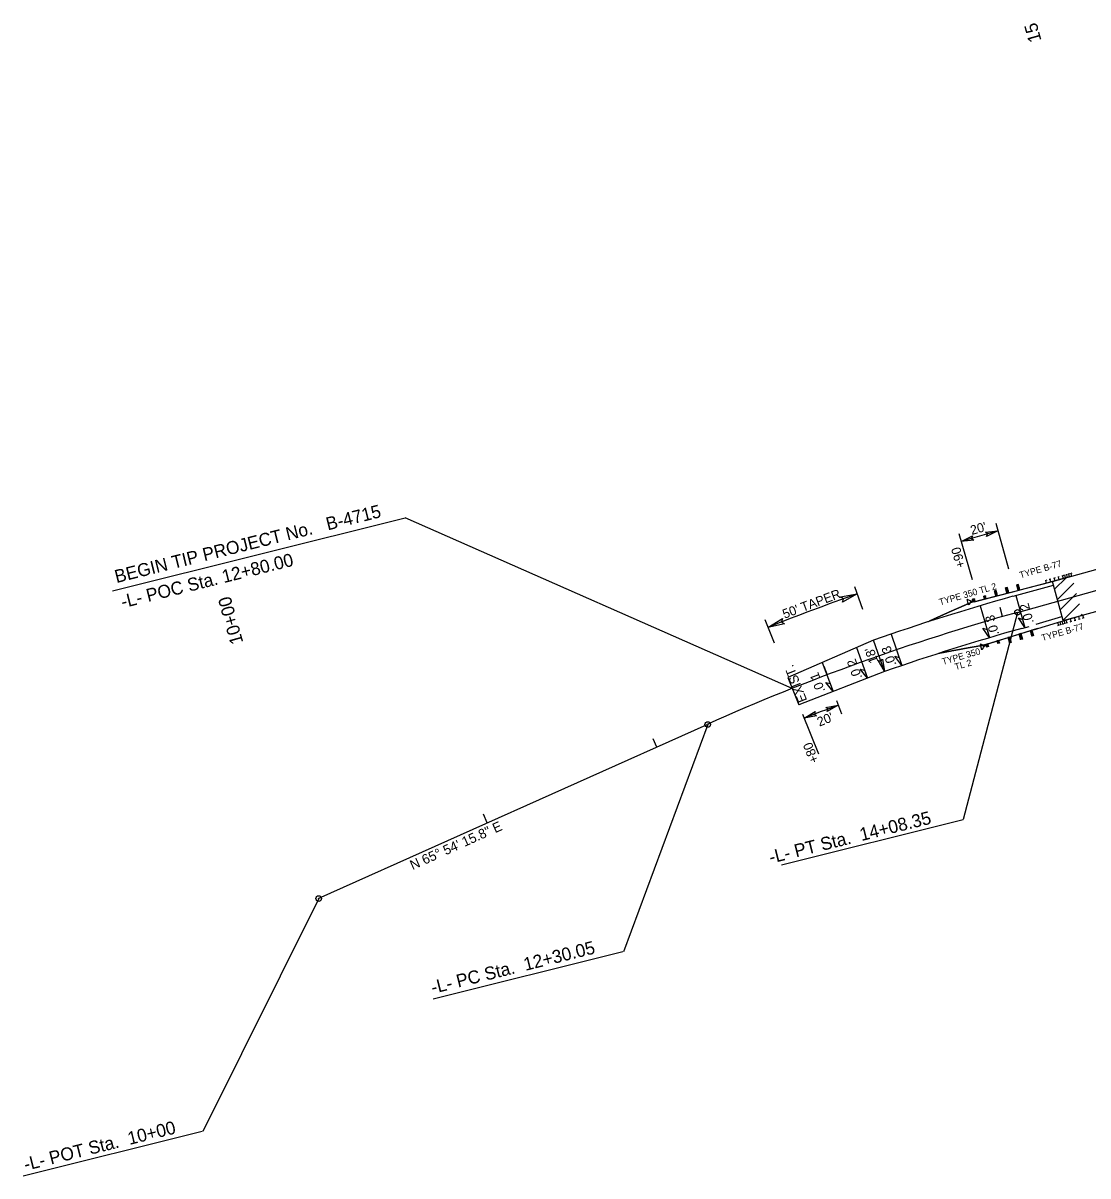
# Model space of a CAD drawing. Extents: x 1030774 to 1032138, y 656382 to 657027.
# Drawn here: x 1030774 to 1031349, y 656382 to 657004 of the extents above; entities that cross this region are included whole.
import ezdxf

# ---------------------------------------------------------------- set-up
doc = ezdxf.new("R2010")
doc.units = 0
for name, color, linetype in [('Prop Approach Slab', 7, 'Continuous'), ('Prop Approach Slab Hatching', 7, 'Continuous'), ('Prop Dimension Text', 7, 'Continuous'), ('Prop EOT', 7, 'Continuous'), ('Prop Guardrail', 7, 'Continuous'), ('Prop Guardrail Anchor Unit CELL', 7, 'Continuous'), ('Prop Horizontal Alignment', 7, 'Continuous'), ('Prop Horizontal Alignment Direction Label', 7, 'Continuous'), ('Prop Horizontal Alignment Station Label', 7, 'Continuous'), ('Prop Horizontal Alignment Tick Label', 7, 'Continuous'), ('Prop Horizontal Alignment Tick Small', 7, 'Continuous'), ('Prop Paved Shoulder', 7, 'Continuous'), ('Prop Roadway Bridge', 7, 'Continuous'), ('Prop SBG', 7, 'Continuous'), ('Prop Structure Anchor Unit CELL', 7, 'Continuous'), ('Prop Superelevation  Arrow CELL', 7, 'Continuous'), ('Prop Superelevation Label', 7, 'Continuous'), ('Prop Terminator CELL', 7, 'Continuous')]:
    doc.layers.add(name, color=color, linetype=linetype)

msp = doc.modelspace()

# ---------------------------------------------------------------- linework, layer by layer
at = {"layer": 'Prop Approach Slab'}
for p, q in [((1031329.55, 656702.31), (1031340.03, 656705.23)), ((1031335.42, 656681.27), (1031329.55, 656702.31)), ((1031335.42, 656681.27), (1031345.9, 656684.2))]:
    msp.add_line(p, q, dxfattribs=at)
at = {"layer": 'Prop Approach Slab Hatching'}
for p, q in [((1031330.77, 656698.17), (1031336.99, 656704.38)), ((1031332.32, 656692.64), (1031341.09, 656701.42)), ((1031333.86, 656687.11), (1031342.63, 656695.89)), ((1031335.4, 656681.59), (1031344.18, 656690.36)), ((1031344.77, 656683.88), (1031345.72, 656684.83))]:
    msp.add_line(p, q, dxfattribs=at)
at = {"layer": 'Prop Dimension Text'}
for p, q in [((1031227.25, 656687.19), (1031222.95, 656699.45)), ((1031174.37, 656681.8), (1031179.35, 656669.32)), ((1031238.98, 656653.74), (1031233.02, 656670.72))]:
    msp.add_line(p, q, dxfattribs=at)
msp.add_arc((1031633.08, 655529.83), 1235.44, 109.32356, 111.71226, dxfattribs=at)
at = {"layer": 'Prop EOT'}
for p, q in [((1031308.32, 656694.4), (1031330.13, 656700.48)), ((1031313.15, 656677.06), (1031316.96, 656678.12)), ((1031233.02, 656670.72), (1031186.82, 656650.61)), ((1031186.82, 656650.61), (1031192.7, 656635.85)), ((1031238.99, 656653.74), (1031192.7, 656635.85))]:
    msp.add_line(p, q, dxfattribs=at)
for radius, end in [(1209, 109.32387), (1191, 109.32325)]:
    msp.add_arc((1031633.08, 655529.83), radius, 105.58244, end, dxfattribs=at)
at = {"layer": 'Prop Guardrail'}
for p, q in [((1031326.48, 656701.46), (1031312.07, 656697.79)), ((1031319.43, 656676.32), (1031332.29, 656680.23))]:
    msp.add_line(p, q, dxfattribs=at)
at = {"layer": 'Prop Guardrail Anchor Unit CELL'}
for p, q in [((1031305.26, 656699.2), (1031304.29, 656698.95)), ((1031305.04, 656696.01), (1031304.29, 656698.95)), ((1031304.29, 656698.95), (1031305.64, 656697.73)), ((1031304.67, 656697.48), (1031305.26, 656699.2)), ((1031306.01, 656696.26), (1031305.26, 656699.2)), ((1031311.31, 656700.75), (1031310.35, 656700.5)), ((1031311.1, 656697.56), (1031310.35, 656700.5)), ((1031310.35, 656700.5), (1031311.69, 656699.28)), ((1031310.72, 656699.03), (1031311.31, 656700.75)), ((1031311.69, 656699.28), (1031310.72, 656699.03)), ((1031312.07, 656697.81), (1031310.72, 656699.03)), ((1031311.69, 656699.28), (1031311.1, 656697.56)), ((1031312.07, 656697.81), (1031311.31, 656700.75)), ((1031283.8, 656692.74), (1031283.5, 656692.66)), ((1031283.8, 656692.74), (1031285.15, 656692.2)), ((1031287.47, 656693.08), (1031286.5, 656692.84)), ((1031286.88, 656691.36), (1031286.5, 656692.84)), ((1031287.85, 656691.61), (1031286.5, 656692.84)), ((1031287.47, 656693.08), (1031286.88, 656691.36)), ((1031287.36, 656691.49), (1031311.58, 656697.68)), ((1031287.85, 656691.61), (1031287.47, 656693.08)), ((1031293.53, 656694.63), (1031292.56, 656694.38)), ((1031292.93, 656692.91), (1031292.56, 656694.38)), ((1031293.9, 656693.16), (1031292.56, 656694.38)), ((1031293.53, 656694.63), (1031292.93, 656692.91)), ((1031293.9, 656693.16), (1031292.93, 656692.91)), ((1031293.9, 656693.16), (1031293.53, 656694.63)), ((1031299.2, 656697.65), (1031298.24, 656697.4)), ((1031298.99, 656694.46), (1031298.24, 656697.4)), ((1031298.24, 656697.4), (1031299.58, 656696.18)), ((1031298.61, 656695.93), (1031299.2, 656697.65)), ((1031299.58, 656696.18), (1031298.61, 656695.93)), ((1031299.96, 656694.71), (1031298.61, 656695.93)), ((1031299.58, 656696.18), (1031298.99, 656694.46)), ((1031299.96, 656694.71), (1031298.99, 656694.46)), ((1031299.96, 656694.71), (1031299.2, 656697.65)), ((1031305.64, 656697.73), (1031304.67, 656697.48)), ((1031306.01, 656696.26), (1031304.67, 656697.48)), ((1031305.64, 656697.73), (1031305.04, 656696.01)), ((1031306.01, 656696.26), (1031305.04, 656696.01)), ((1031312.07, 656697.81), (1031311.1, 656697.56)), ((1031284.22, 656689.81), (1031283.5, 656692.66)), ((1031284.52, 656689.89), (1031284.22, 656689.81)), ((1031285.45, 656691.01), (1031284.52, 656689.89)), ((1031285.15, 656692.2), (1031285.45, 656691.01)), ((1031285.27, 656691.71), (1031286.7, 656692.07)), ((1031286.88, 656691.37), (1031285.45, 656691.01)), ((1031287.85, 656691.61), (1031286.88, 656691.36)), ((1031294.09, 656668.6), (1031317.99, 656675.92)), ((1031312.49, 656674.24), (1031311.54, 656673.95)), ((1031312.49, 656674.24), (1031311.98, 656672.5)), ((1031312.49, 656674.24), (1031313.38, 656671.34)), ((1031318.47, 656676.07), (1031317.51, 656675.78)), ((1031317.51, 656675.78), (1031318.4, 656672.88)), ((1031318.91, 656674.62), (1031317.51, 656675.78)), ((1031318.47, 656676.07), (1031317.96, 656674.33)), ((1031318.91, 656674.62), (1031317.96, 656674.33)), ((1031317.96, 656674.33), (1031319.36, 656673.17)), ((1031318.4, 656672.88), (1031318.91, 656674.62)), ((1031318.47, 656676.07), (1031319.36, 656673.17)), ((1031290.83, 656668.49), (1031290.54, 656668.4)), ((1031290.54, 656668.4), (1031291.4, 656665.59)), ((1031292.21, 656668.01), (1031290.83, 656668.49)), ((1031293.61, 656668.44), (1031292.21, 656668.01)), ((1031292.57, 656666.84), (1031292.21, 656668.01)), ((1031294.57, 656668.75), (1031293.61, 656668.45)), ((1031293.61, 656668.45), (1031294.05, 656667)), ((1031295.01, 656667.3), (1031293.61, 656668.45)), ((1031294.57, 656668.75), (1031294.05, 656667)), ((1031294.57, 656668.75), (1031295.01, 656667.3)), ((1031300.54, 656670.58), (1031299.58, 656670.28)), ((1031299.58, 656670.28), (1031300.03, 656668.83)), ((1031300.99, 656669.13), (1031299.58, 656670.28)), ((1031300.54, 656670.58), (1031300.03, 656668.83)), ((1031300.99, 656669.13), (1031300.03, 656668.83)), ((1031300.54, 656670.58), (1031300.99, 656669.13)), ((1031306.52, 656672.41), (1031305.56, 656672.12)), ((1031305.56, 656672.12), (1031306.45, 656669.21)), ((1031306.96, 656670.96), (1031305.56, 656672.12)), ((1031306.52, 656672.41), (1031306.01, 656670.66)), ((1031306.96, 656670.96), (1031306.01, 656670.66)), ((1031306.01, 656670.66), (1031307.41, 656669.51)), ((1031306.45, 656669.21), (1031306.96, 656670.96)), ((1031307.41, 656669.51), (1031306.45, 656669.21)), ((1031306.52, 656672.41), (1031307.41, 656669.51)), ((1031311.54, 656673.95), (1031312.43, 656671.04)), ((1031312.94, 656672.79), (1031311.54, 656673.95)), ((1031312.94, 656672.79), (1031311.98, 656672.5)), ((1031311.98, 656672.5), (1031313.38, 656671.34)), ((1031312.43, 656671.04), (1031312.94, 656672.79)), ((1031313.38, 656671.34), (1031312.43, 656671.04)), ((1031319.36, 656673.17), (1031318.4, 656672.88)), ((1031291.69, 656665.68), (1031291.4, 656665.59)), ((1031291.69, 656665.68), (1031292.57, 656666.84)), ((1031292.42, 656667.32), (1031293.82, 656667.76)), ((1031295.01, 656667.3), (1031294.05, 656667))]:
    msp.add_line(p, q, dxfattribs=at)
at = {"layer": 'Prop Horizontal Alignment'}
for p, q in [((1031310.74, 656685.73), (1031475.4, 656731.65)), ((1030933.16, 656531.35), (1031143.17, 656625.27))]:
    msp.add_line(p, q, dxfattribs=at)
msp.add_arc((1031633.09, 655529.83), 1200, 105.58243, 114.09562, dxfattribs=at)
at = {"layer": 'Prop Horizontal Alignment Station Label'}
for p, q in [((1030822.29, 656697.3), (1030980.18, 656736.67)), ((1031189.18, 656644.71), (1030980.18, 656736.67)), ((1031310.74, 656685.73), (1031281.34, 656573.84)), ((1031143.54, 656625.18), (1031098.1, 656502.57)), ((1031183.41, 656549.43), (1031281.34, 656573.84)), ((1030933.53, 656531.26), (1030870.95, 656405.55)), ((1030995.33, 656477.13), (1031097.74, 656502.67)), ((1030773.93, 656381.55), (1030870.59, 656405.65))]:
    msp.add_line(p, q, dxfattribs=at)
for centre in [(1031310.74, 656685.73), (1031143.54, 656625.18), (1030933.53, 656531.26)]:
    msp.add_circle(centre, 1.5, dxfattribs=at)
at = {"layer": 'Prop Horizontal Alignment Tick Small'}
for p, q in [((1031302.7, 656683.45), (1031301.32, 656688.26)), ((1031208.18, 656651.86), (1031206.41, 656656.53)), ((1031116.1, 656612.91), (1031114.06, 656617.47)), ((1031024.45, 656572.18), (1031022.41, 656576.74))]:
    msp.add_line(p, q, dxfattribs=at)
at = {"layer": 'Prop Paved Shoulder'}
for p, q in [((1031285.45, 656691.01), (1031329.55, 656702.31)), ((1031321.53, 656676.97), (1031292.36, 656667.92))]:
    msp.add_line(p, q, dxfattribs=at)
for points in [[(1031285.47, 656690.91), (1031285.16, 656690.78), (1031284.84, 656690.64), (1031284.52, 656690.5), (1031284.21, 656690.37), (1031283.89, 656690.23), (1031283.58, 656690.09), (1031283.26, 656689.95), (1031282.94, 656689.82), (1031282.63, 656689.68), (1031282.31, 656689.54), (1031282, 656689.4), (1031281.68, 656689.26), (1031281.37, 656689.13), (1031281.05, 656688.99), (1031280.73, 656688.85), (1031280.42, 656688.71), (1031280.1, 656688.57), (1031279.79, 656688.43), (1031279.47, 656688.3), (1031279.16, 656688.16), (1031278.84, 656688.02), (1031278.53, 656687.88), (1031278.21, 656687.74), (1031277.9, 656687.6), (1031277.58, 656687.46), (1031277.27, 656687.32), (1031276.95, 656687.18), (1031276.64, 656687.04), (1031276.32, 656686.9), (1031276.01, 656686.77), (1031275.69, 656686.63), (1031275.38, 656686.49), (1031275.06, 656686.35), (1031274.75, 656686.21), (1031274.43, 656686.07), (1031274.12, 656685.93), (1031273.8, 656685.79), (1031273.49, 656685.65), (1031273.18, 656685.51), (1031272.86, 656685.37), (1031272.55, 656685.22), (1031272.23, 656685.08), (1031271.92, 656684.94), (1031271.6, 656684.8), (1031271.29, 656684.66), (1031270.98, 656684.52), (1031270.66, 656684.38), (1031270.35, 656684.24), (1031270.04, 656684.1), (1031269.72, 656683.96), (1031269.41, 656683.82), (1031269.09, 656683.67), (1031268.78, 656683.53), (1031268.47, 656683.39), (1031268.15, 656683.25), (1031267.84, 656683.11), (1031267.53, 656682.97), (1031267.21, 656682.82), (1031266.9, 656682.68), (1031266.59, 656682.54), (1031266.27, 656682.4), (1031265.96, 656682.25), (1031265.65, 656682.11), (1031265.33, 656681.97), (1031265.02, 656681.83), (1031264.71, 656681.68), (1031264.39, 656681.54), (1031264.08, 656681.4), (1031263.77, 656681.26), (1031263.46, 656681.11), (1031263.14, 656680.97), (1031262.83, 656680.83), (1031262.21, 656680.54)], [(1031292.36, 656667.92), (1031292.02, 656667.87), (1031291.69, 656667.81), (1031291.36, 656667.75), (1031291.02, 656667.69), (1031290.69, 656667.63), (1031290.36, 656667.58), (1031290.03, 656667.52), (1031289.69, 656667.46), (1031289.36, 656667.4), (1031289.03, 656667.34), (1031288.69, 656667.29), (1031288.36, 656667.23), (1031288.03, 656667.17), (1031287.69, 656667.11), (1031287.36, 656667.05), (1031287.03, 656666.99), (1031286.7, 656666.93), (1031286.36, 656666.87), (1031286.03, 656666.81), (1031285.7, 656666.76), (1031285.36, 656666.7), (1031285.03, 656666.64), (1031284.7, 656666.58), (1031284.37, 656666.52), (1031284.03, 656666.46), (1031283.7, 656666.4), (1031283.37, 656666.34), (1031283.03, 656666.28), (1031282.7, 656666.22), (1031282.37, 656666.16), (1031282.03, 656666.1), (1031281.7, 656666.04), (1031281.37, 656665.98), (1031281.04, 656665.92), (1031280.7, 656665.85), (1031280.37, 656665.79), (1031280.04, 656665.73), (1031279.7, 656665.67), (1031279.37, 656665.61), (1031279.04, 656665.55), (1031278.71, 656665.49), (1031278.37, 656665.43), (1031278.04, 656665.36), (1031277.71, 656665.3), (1031277.38, 656665.24), (1031277.04, 656665.18), (1031276.71, 656665.12), (1031276.38, 656665.06), (1031276.04, 656664.99), (1031275.71, 656664.93), (1031275.38, 656664.87), (1031275.05, 656664.81), (1031274.71, 656664.74), (1031274.38, 656664.68), (1031274.05, 656664.62), (1031273.71, 656664.56), (1031273.38, 656664.49), (1031273.05, 656664.43), (1031272.72, 656664.37), (1031272.38, 656664.3), (1031272.05, 656664.24), (1031271.72, 656664.18), (1031271.39, 656664.11), (1031271.05, 656664.05), (1031270.72, 656663.99), (1031270.39, 656663.92), (1031270.06, 656663.86), (1031269.72, 656663.79), (1031269.39, 656663.73), (1031269.06, 656663.67), (1031268.72, 656663.6), (1031268.39, 656663.54), (1031267.73, 656663.41)]]:
    msp.add_spline(points, degree=3, dxfattribs=at)
at = {"layer": 'Prop Roadway Bridge'}
for p, q in [((1031340.03, 656705.23), (1031457.91, 656738.11)), ((1031345.9, 656684.2), (1031463.78, 656717.07))]:
    msp.add_line(p, q, dxfattribs=at)
at = {"layer": 'Prop SBG'}
msp.add_line((1031320.85, 656679.4), (1031334.75, 656683.49), dxfattribs=at)
at = {"layer": 'Prop Structure Anchor Unit CELL'}
for p, q in [((1031340.03, 656705.23), (1031326.48, 656701.46)), ((1031335.52, 656705.53), (1031334.7, 656705.3)), ((1031335.51, 656703.97), (1031335.11, 656705.42)), ((1031336.65, 656705.85), (1031335.83, 656705.62)), ((1031336.64, 656704.29), (1031336.24, 656705.73)), ((1031337.78, 656706.16), (1031336.95, 656705.93)), ((1031337.77, 656704.6), (1031337.37, 656706.05)), ((1031338.91, 656706.48), (1031338.08, 656706.25)), ((1031338.9, 656704.92), (1031338.5, 656706.36)), ((1031340.04, 656706.79), (1031339.21, 656706.56)), ((1031340.03, 656705.23), (1031339.63, 656706.68)), ((1031326.49, 656703.02), (1031325.67, 656702.78)), ((1031326.48, 656701.46), (1031326.08, 656702.9)), ((1031328.75, 656703.64), (1031327.92, 656703.41)), ((1031328.74, 656702.08), (1031328.34, 656703.53)), ((1031331.01, 656704.27), (1031330.18, 656704.04)), ((1031331, 656702.71), (1031330.6, 656704.16)), ((1031333.27, 656704.9), (1031332.44, 656704.67)), ((1031333.26, 656703.34), (1031332.85, 656704.79)), ((1031332.42, 656680.27), (1031345.91, 656684.22)), ((1031333.54, 656680.6), (1031333.96, 656679.16)), ((1031334.67, 656680.93), (1031335.09, 656679.49)), ((1031335.79, 656681.26), (1031336.21, 656679.82)), ((1031336.92, 656681.59), (1031337.34, 656680.15)), ((1031339.17, 656682.24), (1031339.59, 656680.8)), ((1031339.18, 656680.68), (1031340, 656680.93)), ((1031341.42, 656682.9), (1031341.84, 656681.46)), ((1031341.42, 656681.34), (1031342.25, 656681.58)), ((1031343.67, 656683.56), (1031344.09, 656682.12)), ((1031343.67, 656682), (1031344.5, 656682.24)), ((1031345.91, 656684.22), (1031346.34, 656682.78)), ((1031345.92, 656682.66), (1031346.75, 656682.9)), ((1031332.42, 656680.27), (1031332.84, 656678.83)), ((1031332.43, 656678.71), (1031333.25, 656678.95)), ((1031333.55, 656679.04), (1031334.38, 656679.28)), ((1031334.68, 656679.37), (1031335.5, 656679.61)), ((1031335.8, 656679.7), (1031336.63, 656679.94)), ((1031336.93, 656680.03), (1031337.75, 656680.27))]:
    msp.add_line(p, q, dxfattribs=at)
at = {"layer": 'Prop Superelevation  Arrow CELL'}
for p, q in [((1031309.9, 656694.84), (1031314.74, 656677.5)), ((1031290.54, 656689.29), (1031295.64, 656672.03)), ((1031242.54, 656674.02), (1031248.36, 656656.98)), ((1031223.77, 656666.69), (1031229.72, 656650.16)), ((1031205.28, 656658.65), (1031211.21, 656643))]:
    msp.add_line(p, q, dxfattribs=at)
for points in [[(1031314.74, 656677.5), (1031311.2, 656682.74), (1031313.5, 656681.95)], [(1031295.64, 656672.03), (1031292.02, 656677.22), (1031294.33, 656676.46)], [(1031248.36, 656656.98), (1031244.53, 656662.01), (1031246.87, 656661.35)], [(1031229.73, 656650.16), (1031225.81, 656655.13), (1031228.16, 656654.51)], [(1031211.2, 656643), (1031207.22, 656647.91), (1031209.57, 656647.32)]]:
    msp.add_lwpolyline(points, close=True, dxfattribs=at)
at = {"layer": 'Prop Superelevation Label'}
for p, q in [((1031299.02, 656733.87), (1031305.88, 656709.26)), ((1031279.02, 656728.29), (1031286.35, 656703.49)), ((1031213.06, 656638.13), (1031215.79, 656630.91)), ((1031194.71, 656630.81), (1031203.25, 656609.42))]:
    msp.add_line(p, q, dxfattribs=at)
for radius, start, end in [(1245.15, 105.50588, 106.45879), (1182.58, 110.75597, 111.71067)]:
    msp.add_arc((1031633.09, 655529.83), radius, start, end, dxfattribs=at)
at = {"layer": 'Prop Terminator CELL'}
for points in [[(1031287.11, 656724.76), (1031280.3, 656723.96), (1031286.47, 656727.03), (1031285.99, 656725.64)], [(1031293.4, 656728.98), (1031300.21, 656729.66), (1031293.99, 656726.69), (1031294.5, 656728.08)], [(1031215.27, 656694.16), (1031224.28, 656695.67), (1031216.26, 656691.17), (1031216.82, 656693.06)], [(1031184.97, 656679.52), (1031176.04, 656677.62), (1031183.85, 656682.46), (1031183.38, 656680.55)], [(1031237.84, 656660.49), (1031238.98, 656653.74), (1031235.6, 656659.75), (1031237.02, 656659.33)], [(1031202.33, 656629.95), (1031195.62, 656628.53), (1031201.49, 656632.16), (1031201.13, 656630.72)], [(1031207.27, 656634.36), (1031213.99, 656635.67), (1031208.07, 656632.14), (1031208.45, 656633.57)]]:
    msp.add_lwpolyline(points, close=True, dxfattribs=at)

# ---------------------------------------------------------------- texts
at = {"layer": 'Prop Dimension Text'}
for s, rotation, p in [("50' TAPER", 20.53635, (1031185.02, 656682.25)), ("18'", 109.32358, (1031235.67, 656659.2)), ('EXIST.', 111.73146, (1031197.27, 656638.28))]:
    msp.add_text(s, height=5, rotation=rotation, dxfattribs=at).set_placement(p)
at = {"layer": 'Prop Guardrail Anchor Unit CELL'}
for s, p in [('TYPE 350 TL 2', (1031268.94, 656689.52)), ('TYPE 350', (1031270.51, 656657.35)), ('TL 2', (1031277.37, 656654.55))]:
    msp.add_text(s, height=3.5, rotation=16, dxfattribs=at).set_placement(p)
at = {"layer": 'Prop Horizontal Alignment Direction Label'}
msp.add_text('N 65%%d 54\' 15.8" E', height=5.25, rotation=24.09562, dxfattribs=at).set_placement((1030984.23, 656546.59))
at = {"layer": 'Prop Horizontal Alignment Station Label'}
for s, rotation, p in [('BEGIN TIP PROJECT No.   B-4715', 13.98333, (1030824.37, 656701.51)), ('-L- POC Sta. 12+80.00', 13.98333, (1030827.76, 656687.92)), ('-L- PT Sta.  14+08.35', 14, (1031177.58, 656550.06)), ('-L- PC Sta.  12+30.05', 14, (1030995.14, 656479.76)), ('-L- POT Sta.  10+00', 14, (1030775.35, 656384.29))]:
    msp.add_text(s, height=7, rotation=rotation, dxfattribs=at).set_placement(p)
at = {"layer": 'Prop Horizontal Alignment Tick Label'}
for s, p in [('15', (1031323.76, 656994.44)), ('10+00', (1030892.87, 656669.55))]:
    msp.add_text(s, height=7, rotation=105.58243, dxfattribs=at).set_placement(p)
at = {"layer": 'Prop Structure Anchor Unit CELL'}
for p in [(1031312.36, 656704.1), (1031324.25, 656670.18)]:
    msp.add_text('TYPE B-77', height=3.5, rotation=16, dxfattribs=at).set_placement(p)
at = {"layer": 'Prop Superelevation Label'}
for s, rotation, p in [("20'", 15.58243, (1031286.04, 656727.46)), ('+90', 105.58243, (1031282.68, 656710.48)), ('.0 2', 105.58244, (1031319.58, 656680.37)), ('.0 3', 105.58244, (1031300.91, 656674.02)), ('.0 3', 108.84611, (1031245.47, 656657.55)), ('.0 2', 109.80104, (1031226.97, 656650.6)), ('.0 1', 110.75597, (1031207.02, 656643.38)), ("20'", 22.25213, (1031203.81, 656623.99)), ('+80', 111.74813, (1031203.65, 656605.55))]:
    msp.add_text(s, height=5, rotation=rotation, dxfattribs=at).set_placement(p)

doc.saveas('drawing.dxf')
